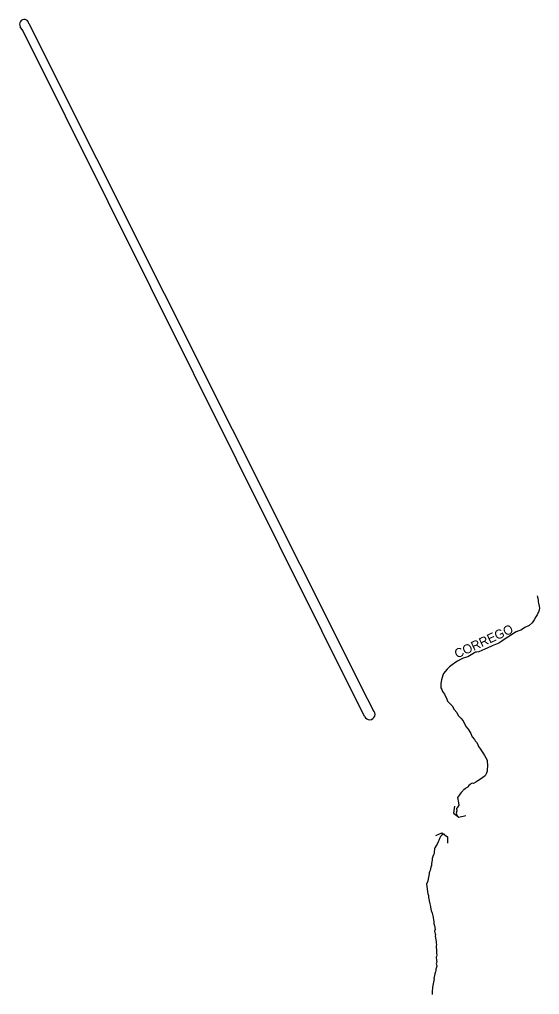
# Model space of a CAD drawing. Extents: x 325899 to 364828, y 7568995 to 7592502.
# Drawn here: x 338821.6 to 339049.8, y 7582049.4 to 7582477.3 of the extents above; entities that cross this region are included whole.
import ezdxf

# ---------------------------------------------------------------- set-up
doc = ezdxf.new("R2010")
doc.units = 0
for name, color, linetype in [('EDIFEXISTENT', 7, 'Continuous'), ('EDIFIDENTIF', 7, 'Continuous'), ('EDIFOBRAEXIS', 7, 'Continuous')]:
    doc.layers.add(name, color=color, linetype=linetype)

msp = doc.modelspace()

# ---------------------------------------------------------------- linework, layer by layer
at = {"layer": 'EDIFEXISTENT'}
for p, q in [((339012.58, 7582131.97), (339012.14, 7582129)), ((339012.14, 7582129), (339014.43, 7582127.14)), ((339014.43, 7582127.14), (339017.49, 7582128)), ((339004.33, 7582119.21), (339006.97, 7582120.29)), ((339006.97, 7582120.29), (339009.49, 7582118.5)), ((339009.49, 7582118.5), (339009.43, 7582115.77))]:
    msp.add_line(p, q, dxfattribs=at)
at = {"layer": 'EDIFOBRAEXIS'}
for points in [[(338973.07, 7582171.41), (338823.05, 7582472.47), (338821.97, 7582474.08)], [(338825.77, 7582475.59), (338974.27, 7582178.95), (338976.88, 7582174.14)], [(339048.85, 7582224.33), (339048.98, 7582223.82), (339049.12, 7582223.26), (339049.16, 7582222.34), (339049.18, 7582221.68), (339049.35, 7582221.15), (339049.64, 7582219.85), (339049.81, 7582218.93), (339049.49, 7582217.64), (339048.76, 7582216.04), (339048.24, 7582215.14), (339047.47, 7582213.77), (339046.61, 7582212.54), (339045.23, 7582211.36), (339043.44, 7582210.51), (339042.29, 7582209.71), (339041.57, 7582209.26), (339040.7, 7582208.99), (339039.53, 7582208.47), (339037.64, 7582207.35), (339037.05, 7582206.92), (339034.79, 7582205.42), (339033.29, 7582204.47), (339032.03, 7582203.62), (339029.04, 7582202.33), (339026.9, 7582201.39), (339025.88, 7582201), (339023.12, 7582199.83), (339022.2, 7582199.66), (339021.62, 7582199.57), (339021.28, 7582199.39), (339018.34, 7582197.6), (339016.38, 7582196.98), (339015.18, 7582196.34), (339013.9, 7582195.74), (339013.11, 7582195.27), (339011.47, 7582193.99), (339010.31, 7582193.14), (339009.36, 7582192.18), (339007.71, 7582190.22), (339007.4, 7582189.53), (339006.79, 7582187.46), (339006.52, 7582185.88), (339006.58, 7582183.95), (339006.98, 7582183.24), (339007.3, 7582182.29), (339008.15, 7582181.16), (339009.09, 7582178.92), (339009.44, 7582178.07), (339010.34, 7582177.3), (339011.47, 7582176.04), (339012.4, 7582174.51), (339013.55, 7582173.1), (339014.12, 7582171.8), (339015.3, 7582170.59), (339016.36, 7582169.43), (339017.47, 7582167.03), (339018.53, 7582165.85), (339019.3, 7582164.67), (339019.75, 7582163.98), (339020.17, 7582162.76), (339020.32, 7582162.43), (339021.32, 7582161.35), (339021.62, 7582160.76), (339022.1, 7582160.09), (339022.82, 7582159.09), (339023.04, 7582158.25), (339023.95, 7582157.07), (339024.32, 7582156.26), (339025.24, 7582155), (339025.67, 7582154.29), (339026.84, 7582152.29), (339026.91, 7582151.86), (339026.97, 7582149.75), (339026.9, 7582147.99), (339026.92, 7582147.46), (339026.57, 7582146.52), (339025.93, 7582145.34), (339025.49, 7582145.09), (339024.9, 7582144.64), (339023.95, 7582143.91), (339022.7, 7582143.08), (339021.86, 7582142.61), (339020.78, 7582141.99), (339020.22, 7582142.15), (339019.69, 7582141.82), (339019.38, 7582141.49), (339018.86, 7582141.04), (339018.38, 7582140.51), (339018.09, 7582140.24), (339017.51, 7582139.91), (339017.22, 7582139.69), (339016.66, 7582139.24), (339016.38, 7582139.04), (339016.15, 7582138.73), (339015.94, 7582138.48), (339015.37, 7582137.98), (339015.04, 7582137.48), (339014.68, 7582136.97), (339014.32, 7582136.39), (339013.9, 7582135.79), (339013.9, 7582135.79), (339013.9, 7582135.79), (339014.29, 7582133.45), (339014.29, 7582133.45), (339014.39, 7582132.53), (339014.39, 7582132.53), (339013.67, 7582131.31), (339013.37, 7582131), (339013.47, 7582129.99), (339013.24, 7582128.98), (339013.24, 7582128.98), (339013.71, 7582127.81)], [(339008.26, 7582119.61), (339007.6, 7582119.77), (339007.12, 7582119.49), (339006.4, 7582118.76), (339006.06, 7582118.16), (339005.64, 7582116.89), (339005.3, 7582116.31), (339004.86, 7582115.4), (339004.62, 7582114.89), (339003.93, 7582113.81), (339003.79, 7582113.25), (339003.58, 7582111.88), (339003.52, 7582111.32), (339003.36, 7582110.66), (339003.07, 7582109.96), (339002.78, 7582109.12), (339002.77, 7582108.28), (339002.43, 7582106.91), (339002.42, 7582106.56), (339002.37, 7582106.02), (339002.13, 7582105.21), (339001.86, 7582103.82), (339001.6, 7582103.14), (339001.42, 7582102.83), (339001.34, 7582102.3), (339001.07, 7582100.9), (339000.98, 7582100.07), (339000.82, 7582099.05), (339000.29, 7582097.74), (339000.31, 7582096.82), (339000.69, 7582094.53), (339000.86, 7582093.54), (339001.05, 7582092.77), (339001.07, 7582091.76), (339001.24, 7582091.5), (339001.41, 7582090.51), (339001.7, 7582089.21), (339001.94, 7582087.96), (339002.01, 7582087.68), (339002.25, 7582086.23), (339002.72, 7582085.1), (339002.92, 7582084.44), (339002.99, 7582083.83), (339003.16, 7582083.17), (339003.32, 7582082), (339003.4, 7582081.72), (339003.44, 7582081.41), (339003.51, 7582080.52), (339003.81, 7582079.58), (339003.88, 7582079.19), (339003.95, 7582078.69), (339004.01, 7582077.85), (339003.73, 7582077.14), (339004.1, 7582076.02), (339004.12, 7582075.63), (339003.98, 7582075), (339004.52, 7582072.61), (339004.43, 7582071.92), (339004.6, 7582071.26), (339004.47, 7582070.67), (339004.43, 7582069.81), (339004.58, 7582069.07), (339004.65, 7582068.74), (339004.67, 7582068.03), (339004.64, 7582067.5), (339004.76, 7582066.6), (339004.55, 7582066.05), (339004.52, 7582065.74), (339004.63, 7582064.24), (339004.7, 7582063.99), (339004.59, 7582063.23), (339004.54, 7582062.9), (339004.66, 7582062.54), (339004.7, 7582061.85), (339004.31, 7582060.51), (339004.3, 7582060.23), (339004.33, 7582059.95), (339004.14, 7582059.34), (339003.83, 7582058.41), (339003.69, 7582057.7), (339003.47, 7582056.45), (339003.55, 7582056.2), (339003.3, 7582054.73), (339003.12, 7582054.07), (339002.96, 7582053.28), (339002.87, 7582052.57), (339002.79, 7582051.94), (339002.68, 7582051.1), (339002.77, 7582050.54), (339002.74, 7582049.37)]]:
    msp.add_lwpolyline(points, dxfattribs=at)
for centre, radius, start, end in [((338823.72, 7582475.21), 2.08, 10.6809, 212.6836), ((338975.26, 7582172.38), 2.39, 204.0562, 47.325)]:
    msp.add_arc(centre, radius, start, end, dxfattribs=at)

# ---------------------------------------------------------------- texts
at = {"layer": 'EDIFIDENTIF'}
msp.add_text('CORREGO', height=4, rotation=24.7684, dxfattribs=at).set_placement((339013.61, 7582196.78))

doc.saveas('drawing.dxf')
